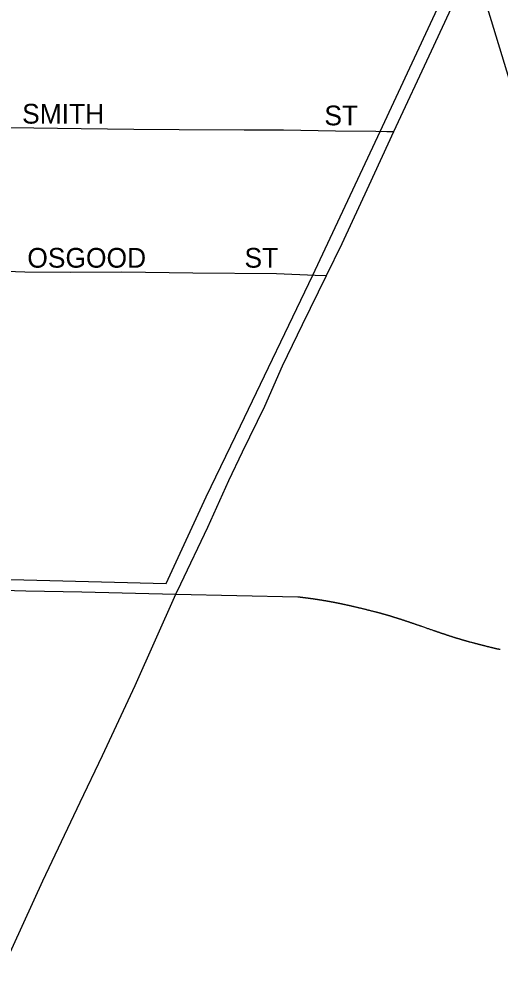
# Model space of a CAD drawing. Extents: x -97 to 34, y -21 to 22.
# Drawn here: x 5.1003 to 5.3311, y 17.7944 to 18.2477 of the extents above; entities that cross this region are included whole.
import ezdxf

# ---------------------------------------------------------------- set-up
doc = ezdxf.new("R2010")
doc.units = 0
for name, color, linetype in [('GM_X_City_Street', 7, 'Continuous'), ('GM_X_City_Street_Text', 7, 'Continuous'), ('GM_X_Corporation', 7, 'Continuous'), ('GM_X_County_Road', 7, 'Continuous'), ('GM_X_Rail_Line', 7, 'Continuous'), ('GM_X_State_Route', 7, 'Continuous')]:
    doc.layers.add(name, color=color, linetype=linetype)

msp = doc.modelspace()

# ---------------------------------------------------------------- linework, layer by layer
at = {"layer": 'GM_X_City_Street'}
for points in [[(5.08014, 18.19589), (5.08367, 18.19579), (5.09613, 18.19548), (5.13016, 18.19507), (5.15536, 18.19473), (5.17721, 18.19458), (5.20843, 18.19448), (5.22716, 18.19443), (5.25211, 18.19399), (5.27146, 18.19375), (5.27676, 18.19362), (5.28022, 18.19353)], [(5.0797, 18.12705), (5.08502, 18.12687), (5.10318, 18.12627), (5.12505, 18.12611), (5.14974, 18.12618), (5.1837, 18.12578), (5.22383, 18.12537), (5.24234, 18.12468), (5.24782, 18.12447)]]:
    msp.add_lwpolyline(points, dxfattribs=at)
at = {"layer": 'GM_X_Corporation'}
msp.add_lwpolyline([(5.07769, 17.97895), (5.17097, 17.97664), (5.19015, 18.01823), (5.20652, 18.05232), (5.24124, 18.1246), (5.27354, 18.19364), (5.30549, 18.26216)], dxfattribs=at)
at = {"layer": 'GM_X_County_Road'}
for points in [[(5.07773, 17.97367), (5.08724, 17.97354), (5.10368, 17.97317)], [(5.10368, 17.97317), (5.13055, 17.97256), (5.17554, 17.97157)], [(5.17554, 17.97157), (5.23412, 17.97027), (5.23435, 17.97025), (5.23457, 17.97022), (5.23479, 17.97019), (5.23501, 17.97017), (5.23523, 17.97014), (5.23545, 17.97011), (5.23567, 17.97009), (5.23588, 17.97006), (5.2361, 17.97003), (5.23632, 17.97001), (5.23653, 17.96998), (5.23674, 17.96995), (5.23695, 17.96993), (5.23716, 17.96989), (5.23738, 17.96987), (5.23759, 17.96984), (5.23779, 17.96981), (5.238, 17.96979), (5.23821, 17.96976), (5.23841, 17.96973), (5.23862, 17.96971), (5.23882, 17.96968), (5.23903, 17.96965), (5.23923, 17.96962), (5.23943, 17.9696), (5.23964, 17.96957), (5.23984, 17.96954), (5.24003, 17.96952), (5.24023, 17.96948), (5.24043, 17.96946), (5.24063, 17.96943), (5.24083, 17.9694), (5.24102, 17.96938), (5.24122, 17.96935), (5.24141, 17.96932), (5.24161, 17.96929), (5.24181, 17.96926), (5.242, 17.96924), (5.24219, 17.9692), (5.24238, 17.96918), (5.24258, 17.96915), (5.24277, 17.96912), (5.24296, 17.96909), (5.24315, 17.96907), (5.24334, 17.96904), (5.24353, 17.96901), (5.24371, 17.96898), (5.24391, 17.96895), (5.24409, 17.96892), (5.24428, 17.96889), (5.24447, 17.96886), (5.24465, 17.96883), (5.24483, 17.96881), (5.24502, 17.96878), (5.2452, 17.96875), (5.24538, 17.96871), (5.24557, 17.96869), (5.24575, 17.96866), (5.24594, 17.96863), (5.24602, 17.96861), (5.24612, 17.9686), (5.24621, 17.96858), (5.2463, 17.96857), (5.24639, 17.96855), (5.24648, 17.96854), (5.24657, 17.96852), (5.24666, 17.96851), (5.24675, 17.9685), (5.24684, 17.96848), (5.247, 17.96845), (5.24717, 17.96842), (5.24733, 17.9684), (5.24749, 17.96837), (5.24765, 17.96834), (5.24782, 17.96831), (5.24798, 17.96829), (5.24815, 17.96825), (5.24831, 17.96822), (5.24848, 17.96819), (5.24865, 17.96817), (5.24881, 17.96814), (5.24898, 17.96811), (5.24914, 17.96807), (5.24931, 17.96804), (5.24948, 17.96802), (5.24965, 17.96799), (5.24982, 17.96796), (5.24998, 17.96792), (5.25015, 17.96789), (5.25032, 17.96786), (5.25049, 17.96783), (5.25066, 17.96779), (5.25083, 17.96776), (5.251, 17.96773), (5.25117, 17.96769), (5.25134, 17.96766), (5.25151, 17.96763), (5.25168, 17.9676), (5.25185, 17.96756), (5.25203, 17.96753), (5.2522, 17.9675), (5.25237, 17.96747), (5.25254, 17.96743), (5.25272, 17.9674), (5.25289, 17.96736), (5.25307, 17.96732), (5.25325, 17.96729), (5.25342, 17.96725), (5.25359, 17.96722), (5.25377, 17.96718), (5.25395, 17.96715), (5.25413, 17.96711), (5.2543, 17.96707), (5.25448, 17.96704), (5.25466, 17.967), (5.25484, 17.96696), (5.25502, 17.96692), (5.2552, 17.96689), (5.25538, 17.96684), (5.25556, 17.96681), (5.25574, 17.96677), (5.25592, 17.96673), (5.2561, 17.96669), (5.25629, 17.96665), (5.25647, 17.96661), (5.25666, 17.96657), (5.25684, 17.96653), (5.25702, 17.96649), (5.25721, 17.96645), (5.2574, 17.96641), (5.25758, 17.96637), (5.25777, 17.96633), (5.25796, 17.96628), (5.25815, 17.96624), (5.25833, 17.9662), (5.25852, 17.96616), (5.25871, 17.96612), (5.25889, 17.96607), (5.25909, 17.96604), (5.25927, 17.96599), (5.25947, 17.96595), (5.25965, 17.96591), (5.25984, 17.96586), (5.26004, 17.96581), (5.26023, 17.96577), (5.26042, 17.96573), (5.26062, 17.96568), (5.26081, 17.96564), (5.26101, 17.96559), (5.2612, 17.96555), (5.2614, 17.9655), (5.2616, 17.96545), (5.2618, 17.9654), (5.262, 17.96536), (5.26221, 17.96531), (5.2624, 17.96526), (5.26261, 17.96522), (5.26281, 17.96517), (5.26302, 17.96512), (5.26322, 17.96507), (5.26343, 17.96502), (5.26364, 17.96497), (5.26385, 17.96492), (5.26406, 17.96487), (5.26427, 17.96481), (5.26448, 17.96476), (5.26469, 17.96471), (5.2649, 17.96466), (5.26512, 17.96461), (5.26534, 17.96455), (5.26555, 17.9645), (5.26577, 17.96445), (5.26599, 17.9644), (5.26621, 17.96434), (5.26644, 17.96428), (5.26666, 17.96423), (5.26688, 17.96417), (5.26711, 17.96412), (5.26734, 17.96405), (5.26757, 17.964), (5.26781, 17.96394), (5.26805, 17.96388), (5.26828, 17.96382), (5.26852, 17.96376), (5.26876, 17.9637), (5.26901, 17.96364), (5.26925, 17.96358), (5.26951, 17.96351), (5.26975, 17.96345), (5.27001, 17.96338), (5.27027, 17.96332), (5.27053, 17.96325), (5.2708, 17.96318), (5.27107, 17.96312), (5.27135, 17.96305), (5.27163, 17.96297), (5.27191, 17.9629), (5.27199, 17.96288), (5.27206, 17.96286), (5.27213, 17.96284), (5.27221, 17.96282), (5.27228, 17.9628), (5.27235, 17.96279), (5.27243, 17.96277), (5.2725, 17.96275), (5.27258, 17.96273), (5.27265, 17.96271), (5.27273, 17.96269), (5.2728, 17.96267), (5.27287, 17.96265), (5.27295, 17.96263), (5.2731, 17.96259), (5.27325, 17.96255), (5.2734, 17.96251), (5.27355, 17.96247), (5.2737, 17.96243), (5.27385, 17.96239), (5.27401, 17.96234), (5.27415, 17.96231), (5.27431, 17.96226), (5.27446, 17.96222), (5.27461, 17.96218), (5.27476, 17.96214), (5.27492, 17.9621), (5.27507, 17.96205), (5.27522, 17.96201), (5.27538, 17.96197), (5.27553, 17.96192), (5.27569, 17.96188), (5.27584, 17.96184), (5.276, 17.96179), (5.27616, 17.96175), (5.27632, 17.9617), (5.27647, 17.96166), (5.27663, 17.96161), (5.27679, 17.96156), (5.27694, 17.96152), (5.27711, 17.96148), (5.27726, 17.96143), (5.27742, 17.96138), (5.27758, 17.96133), (5.27774, 17.96128), (5.2779, 17.96124), (5.27806, 17.96119), (5.27822, 17.96114), (5.27839, 17.96109), (5.27855, 17.96105), (5.27872, 17.961), (5.27888, 17.96095), (5.27904, 17.9609), (5.27921, 17.96085), (5.27937, 17.96079), (5.27954, 17.96074), (5.2797, 17.96069), (5.27987, 17.96064), (5.28004, 17.96059), (5.28021, 17.96054), (5.28037, 17.96049), (5.28054, 17.96043), (5.28071, 17.96038), (5.28088, 17.96033), (5.28105, 17.96028), (5.28123, 17.96022), (5.2814, 17.96016), (5.28157, 17.96011), (5.28175, 17.96005), (5.28192, 17.96), (5.2821, 17.95994), (5.28227, 17.95989), (5.28244, 17.95983), (5.28261, 17.95978), (5.28279, 17.95972), (5.28296, 17.95967), (5.28313, 17.95961), (5.28331, 17.95956), (5.28348, 17.95949), (5.28366, 17.95944), (5.28384, 17.95938), (5.28402, 17.95932), (5.2842, 17.95926), (5.28438, 17.9592), (5.28456, 17.95914), (5.28474, 17.95908), (5.28493, 17.95902), (5.28511, 17.95896), (5.2853, 17.9589), (5.28549, 17.95883), (5.28567, 17.95877), (5.28586, 17.95871), (5.28605, 17.95865), (5.28625, 17.95859), (5.28644, 17.95852), (5.28664, 17.95846), (5.28683, 17.95839), (5.28703, 17.95832), (5.28723, 17.95825), (5.28743, 17.95818), (5.28763, 17.95811), (5.28784, 17.95805), (5.28805, 17.95798), (5.28823, 17.95791), (5.28842, 17.95785), (5.28861, 17.95778), (5.28881, 17.95772), (5.289, 17.95765), (5.28919, 17.95759), (5.28939, 17.95752), (5.2896, 17.95745), (5.28979, 17.95737), (5.29, 17.95731), (5.29021, 17.95723), (5.29042, 17.95716), (5.29064, 17.95709), (5.29086, 17.95701), (5.29108, 17.95693), (5.2913, 17.95686), (5.2915, 17.95678), (5.29171, 17.95672), (5.29192, 17.95664), (5.29213, 17.95657), (5.29235, 17.95649), (5.29257, 17.95642), (5.2928, 17.95634), (5.29304, 17.95625), (5.29347, 17.9561), (5.29396, 17.95593), (5.29444, 17.95576), (5.29568, 17.95534), (5.29605, 17.95521), (5.29637, 17.95509), (5.29674, 17.95496), (5.29709, 17.95484), (5.29742, 17.95473), (5.29774, 17.95462), (5.29811, 17.95449), (5.29847, 17.95436), (5.29882, 17.95424), (5.29915, 17.95412), (5.29932, 17.95407), (5.29948, 17.95401), (5.29964, 17.95396), (5.2998, 17.9539), (5.29996, 17.95384), (5.30012, 17.95379), (5.30027, 17.95374), (5.30043, 17.95369), (5.30061, 17.95362), (5.3008, 17.95356), (5.30099, 17.9535), (5.30117, 17.95343), (5.30135, 17.95337), (5.30153, 17.95331), (5.30171, 17.95325), (5.30188, 17.95319), (5.30206, 17.95313), (5.30223, 17.95307), (5.3024, 17.95301), (5.30258, 17.95296), (5.30274, 17.9529), (5.30291, 17.95284), (5.30308, 17.95278), (5.30325, 17.95273), (5.30341, 17.95267), (5.30358, 17.95262), (5.30374, 17.95256), (5.3039, 17.95251), (5.30406, 17.95245), (5.30422, 17.9524), (5.30438, 17.95235), (5.30454, 17.9523), (5.3047, 17.95224), (5.30486, 17.95219), (5.30501, 17.95214), (5.30517, 17.95209), (5.30532, 17.95204), (5.30548, 17.95199), (5.30563, 17.95194), (5.30578, 17.95189), (5.30597, 17.95183), (5.30616, 17.95176), (5.30635, 17.9517), (5.30653, 17.95164), (5.30672, 17.95158), (5.30691, 17.95152), (5.30709, 17.95146), (5.30727, 17.9514), (5.30746, 17.95134), (5.30764, 17.95128), (5.30782, 17.95123), (5.308, 17.95117), (5.30818, 17.95111), (5.30836, 17.95105), (5.30853, 17.951), (5.30871, 17.95094), (5.30885, 17.9509)], [(5.30885, 17.9509), (5.30889, 17.95089), (5.30907, 17.95083), (5.30924, 17.95078), (5.30942, 17.95073), (5.30959, 17.95067), (5.30977, 17.95061), (5.30994, 17.95056), (5.31011, 17.95051), (5.31028, 17.95046), (5.31045, 17.9504), (5.31062, 17.95035), (5.31079, 17.9503), (5.31096, 17.95025), (5.31113, 17.9502), (5.31129, 17.95015), (5.31146, 17.9501), (5.31163, 17.95005), (5.3118, 17.95), (5.31196, 17.94995), (5.31213, 17.9499), (5.31229, 17.94985), (5.31246, 17.9498), (5.31262, 17.94975), (5.31278, 17.94971), (5.31295, 17.94966), (5.31311, 17.94961), (5.31328, 17.94956), (5.31344, 17.94951), (5.3136, 17.94947), (5.31368, 17.94945), (5.31376, 17.94942), (5.31384, 17.9494), (5.31392, 17.94938), (5.314, 17.94935), (5.31408, 17.94933), (5.31416, 17.94931), (5.31424, 17.94928), (5.31432, 17.94927), (5.3144, 17.94924), (5.31448, 17.94922), (5.31456, 17.9492), (5.31464, 17.94917), (5.31472, 17.94915), (5.3148, 17.94913), (5.31488, 17.94911), (5.31495, 17.94908), (5.31503, 17.94907), (5.31512, 17.94904), (5.3152, 17.94902), (5.31527, 17.949), (5.31535, 17.94897), (5.31543, 17.94895), (5.31551, 17.94894), (5.31559, 17.94891), (5.31566, 17.94889), (5.31574, 17.94887), (5.31582, 17.94885), (5.3159, 17.94882), (5.31598, 17.94881), (5.31605, 17.94879), (5.31613, 17.94876), (5.31621, 17.94874), (5.31629, 17.94872), (5.31636, 17.9487), (5.31644, 17.94868), (5.31652, 17.94866), (5.3166, 17.94864), (5.31705, 17.94851), (5.31742, 17.94842), (5.31775, 17.94833), (5.31805, 17.94825), (5.31835, 17.94817), (5.31863, 17.9481), (5.3189, 17.94803), (5.31915, 17.94796), (5.31941, 17.94789), (5.31967, 17.94782), (5.31991, 17.94776), (5.32015, 17.94769), (5.32039, 17.94763), (5.32062, 17.94757), (5.32084, 17.94751), (5.32107, 17.94746), (5.32129, 17.94739), (5.32152, 17.94734), (5.32174, 17.94728), (5.32196, 17.94722), (5.32217, 17.94716), (5.32238, 17.94712), (5.32259, 17.94706), (5.3228, 17.947), (5.323, 17.94695), (5.32321, 17.9469), (5.3234, 17.94685), (5.3236, 17.9468), (5.3238, 17.94675), (5.32399, 17.9467), (5.32419, 17.94665), (5.32438, 17.9466), (5.32458, 17.94655), (5.32478, 17.94651), (5.32497, 17.94646), (5.32516, 17.94641), (5.32536, 17.94636), (5.32555, 17.94631), (5.32573, 17.94626), (5.32592, 17.94622), (5.32611, 17.94618), (5.32629, 17.94613), (5.32648, 17.94608), (5.32667, 17.94604), (5.32685, 17.946), (5.32694, 17.94597), (5.32703, 17.94595), (5.32712, 17.94593), (5.32721, 17.94591), (5.3273, 17.94588), (5.32739, 17.94587), (5.32747, 17.94585), (5.32757, 17.94582), (5.32765, 17.9458), (5.32774, 17.94578), (5.32783, 17.94576), (5.32792, 17.94574), (5.32801, 17.94572), (5.3281, 17.9457), (5.32818, 17.94568), (5.32827, 17.94566), (5.32836, 17.94564), (5.32844, 17.94562), (5.32853, 17.9456), (5.32862, 17.94558), (5.3287, 17.94556), (5.32879, 17.94554), (5.32888, 17.94552), (5.32897, 17.9455), (5.32905, 17.94548), (5.32913, 17.94546), (5.32922, 17.94544), (5.32931, 17.94542), (5.32939, 17.9454), (5.32947, 17.94538), (5.32956, 17.94536), (5.32964, 17.94534), (5.32973, 17.94533), (5.32981, 17.94531), (5.3299, 17.94529), (5.32998, 17.94527), (5.33007, 17.94525), (5.33015, 17.94523), (5.33033, 17.9452), (5.33051, 17.94515), (5.33069, 17.94511), (5.33086, 17.94508), (5.33104, 17.94503), (5.33122, 17.945)]]:
    msp.add_lwpolyline(points, dxfattribs=at)
at = {"layer": 'GM_X_Rail_Line'}
msp.add_lwpolyline([(5.60523, 17.35344), (5.55562, 17.51395), (5.4983, 17.70003), (5.48173, 17.74398), (5.41338, 17.96695), (5.35777, 18.14587), (5.31905, 18.27307), (5.25811, 18.46824), (5.19106, 18.68588), (5.15793, 18.79229), (5.13207, 18.87623), (5.10765, 18.95692), (5.10388, 18.96978), (5.10128, 18.97992), (5.09855, 18.992)], dxfattribs=at)
at = {"layer": 'GM_X_State_Route'}
for points in [[(5.24782, 18.12447), (5.25533, 18.13978), (5.26828, 18.16788), (5.28022, 18.19353), (5.29829, 18.23237), (5.31192, 18.26216), (5.31759, 18.27456), (5.33789, 18.31695)], [(5.12976, 17.87171), (5.14037, 17.89407), (5.15601, 17.9277), (5.17554, 17.97157), (5.17797, 17.97651), (5.19091, 18.00374), (5.20101, 18.02606), (5.20759, 18.03977), (5.21831, 18.06183), (5.22681, 18.08108), (5.23628, 18.10095), (5.24782, 18.12447)], [(4.88389, 17.35344), (4.89794, 17.38191), (4.93367, 17.45431), (4.94238, 17.4719), (4.95297, 17.49329), (4.97868, 17.54641), (5.0051, 17.60264), (5.03382, 17.66463), (5.05224, 17.70403), (5.07816, 17.7605), (5.08347, 17.77208), (5.11182, 17.8339), (5.12976, 17.87171)]]:
    msp.add_lwpolyline(points, dxfattribs=at)

# ---------------------------------------------------------------- texts
at = {"layer": 'GM_X_City_Street_Text'}
for s, p in [('SMITH', (5.10183, 18.19739)), ('ST', (5.24683, 18.19656)), ('OSGOOD', (5.10433, 18.12823)), ('ST', (5.2085, 18.12823))]:
    msp.add_text(s, height=0.00947, rotation=0, dxfattribs=at).set_placement(p)

doc.saveas('drawing.dxf')
